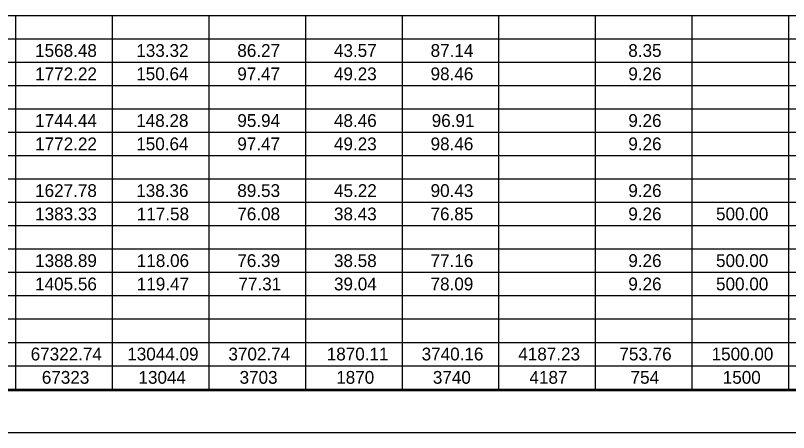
# Model space of a CAD drawing. Extents: x 0 to 34.4, y 0 to 47.
# Drawn here: x 16.38 to 25.65, y 0 to 5 of the extents above; entities that cross this region are included whole.
import ezdxf

# ---------------------------------------------------------------- set-up
doc = ezdxf.new("R2010")
doc.units = 0
for name, color, linetype in [('SH_Border', 7, 'Continuous'), ('SH_Cut_Line', 7, 'Continuous'), ('SH_Text', 7, 'Continuous')]:
    doc.layers.add(name, color=color, linetype=linetype)

msp = doc.modelspace()

# ---------------------------------------------------------------- linework, layer by layer
at = {"layer": 'SH_Border'}
msp.add_lwpolyline([(1.5, 21.5), (33.5, 21.5), (33.5, 0.5), (1.5, 0.5)], close=True, dxfattribs=at)
at = {"layer": 'SH_Cut_Line'}
msp.add_lwpolyline([(0, 0), (34, 0), (34, 22), (0, 22)], close=True, dxfattribs=at)
at = {"layer": 'SH_Text'}
for p, q in [((15.2196, 4.9965), (16.3784, 4.9965)), ((16.3784, 4.9965), (24.4903, 4.9965)), ((16.3784, 4.9965), (16.3784, 4.7168)), ((17.5373, 4.9965), (17.5373, 4.7168)), ((18.6961, 4.9965), (18.6961, 4.7168)), ((19.855, 4.9965), (19.855, 4.7168)), ((21.0138, 4.9965), (21.0138, 4.7168)), ((22.1726, 4.9965), (22.1726, 4.7168)), ((23.3315, 4.9965), (23.3315, 4.7168)), ((24.4903, 4.9965), (25.6492, 4.9965)), ((24.4903, 4.9965), (24.4903, 4.7168)), ((25.6492, 4.9965), (27.9668, 4.9965)), ((25.6492, 4.9965), (25.6492, 4.7168)), ((15.2196, 4.7168), (16.3784, 4.7168)), ((16.3784, 4.7168), (24.4903, 4.7168)), ((16.3784, 4.7168), (16.3784, 4.4371)), ((17.5373, 4.7168), (17.5373, 4.4371)), ((18.6961, 4.7168), (18.6961, 4.4371)), ((19.855, 4.7168), (19.855, 4.4371)), ((21.0138, 4.7168), (21.0138, 4.4371)), ((22.1726, 4.7168), (22.1726, 4.4371)), ((23.3315, 4.7168), (23.3315, 4.4371)), ((24.4903, 4.7168), (25.6492, 4.7168)), ((24.4903, 4.7168), (24.4903, 4.4371)), ((25.6492, 4.7168), (27.9668, 4.7168)), ((25.6492, 4.7168), (25.6492, 4.4371)), ((15.2196, 4.4371), (16.3784, 4.4371)), ((16.3784, 4.4371), (24.4903, 4.4371)), ((16.3784, 4.4371), (16.3784, 4.1574)), ((17.5373, 4.4371), (17.5373, 4.1574)), ((18.6961, 4.4371), (18.6961, 4.1574)), ((19.855, 4.4371), (19.855, 4.1574)), ((21.0138, 4.4371), (21.0138, 4.1574)), ((22.1726, 4.4371), (22.1726, 4.1574)), ((23.3315, 4.4371), (23.3315, 4.1574)), ((24.4903, 4.4371), (25.6492, 4.4371)), ((24.4903, 4.4371), (24.4903, 4.1574)), ((25.6492, 4.4371), (27.9668, 4.4371)), ((25.6492, 4.4371), (25.6492, 4.1574)), ((15.2196, 4.1574), (16.3784, 4.1574)), ((16.3784, 4.1574), (24.4903, 4.1574)), ((16.3784, 4.1574), (16.3784, 3.5979)), ((17.5373, 4.1574), (17.5373, 3.5979)), ((18.6961, 4.1574), (18.6961, 3.5979)), ((19.855, 4.1574), (19.855, 3.5979)), ((21.0138, 4.1574), (21.0138, 3.5979)), ((22.1726, 4.1574), (22.1726, 3.5979)), ((23.3315, 4.1574), (23.3315, 3.5979)), ((24.4903, 4.1574), (25.6492, 4.1574)), ((24.4903, 4.1574), (24.4903, 3.5979)), ((25.6492, 4.1574), (27.9668, 4.1574)), ((25.6492, 4.1574), (25.6492, 3.5979)), ((15.2196, 3.8776), (16.3784, 3.8776)), ((16.3784, 3.8776), (24.4903, 3.8776)), ((24.4903, 3.8776), (25.6492, 3.8776)), ((25.6492, 3.8776), (27.9668, 3.8776)), ((15.2196, 3.5979), (16.3784, 3.5979)), ((16.3784, 3.5979), (24.4903, 3.5979)), ((16.3784, 3.5979), (16.3784, 3.3182)), ((17.5373, 3.5979), (17.5373, 3.3182)), ((18.6961, 3.5979), (18.6961, 3.3182)), ((19.855, 3.5979), (19.855, 3.3182)), ((21.0138, 3.5979), (21.0138, 3.3182)), ((22.1726, 3.5979), (22.1726, 3.3182)), ((23.3315, 3.5979), (23.3315, 3.3182)), ((24.4903, 3.5979), (25.6492, 3.5979)), ((24.4903, 3.5979), (24.4903, 3.3182)), ((25.6492, 3.5979), (27.9668, 3.5979)), ((25.6492, 3.5979), (25.6492, 3.3182)), ((15.2196, 3.3182), (16.3784, 3.3182)), ((16.3784, 3.3182), (24.4903, 3.3182)), ((16.3784, 3.3182), (16.3784, 3.0385)), ((17.5373, 3.3182), (17.5373, 3.0385)), ((18.6961, 3.3182), (18.6961, 3.0385)), ((19.855, 3.3182), (19.855, 3.0385)), ((21.0138, 3.3182), (21.0138, 3.0385)), ((22.1726, 3.3182), (22.1726, 3.0385)), ((23.3315, 3.3182), (23.3315, 3.0385)), ((24.4903, 3.3182), (25.6492, 3.3182)), ((24.4903, 3.3182), (24.4903, 3.0385)), ((25.6492, 3.3182), (27.9668, 3.3182)), ((25.6492, 3.3182), (25.6492, 3.0385)), ((15.2196, 3.0385), (16.3784, 3.0385)), ((16.3784, 3.0385), (24.4903, 3.0385)), ((16.3784, 3.0385), (16.3784, 2.7588)), ((17.5373, 3.0385), (17.5373, 2.7588)), ((18.6961, 3.0385), (18.6961, 2.7588)), ((19.855, 3.0385), (19.855, 2.7588)), ((21.0138, 3.0385), (21.0138, 2.7588)), ((22.1726, 3.0385), (22.1726, 2.7588)), ((23.3315, 3.0385), (23.3315, 2.7588)), ((24.4903, 3.0385), (25.6492, 3.0385)), ((24.4903, 3.0385), (24.4903, 2.7588)), ((25.6492, 3.0385), (27.9668, 3.0385)), ((25.6492, 3.0385), (25.6492, 2.7588)), ((15.2196, 2.7588), (16.3784, 2.7588)), ((16.3784, 2.7588), (24.4903, 2.7588)), ((16.3784, 2.7588), (16.3784, 2.1993)), ((17.5373, 2.7588), (17.5373, 2.1993)), ((18.6961, 2.7588), (18.6961, 2.1993)), ((19.855, 2.7588), (19.855, 2.1993)), ((21.0138, 2.7588), (21.0138, 2.1993)), ((22.1726, 2.7588), (22.1726, 2.1993)), ((23.3315, 2.7588), (23.3315, 2.1993)), ((24.4903, 2.7588), (25.6492, 2.7588)), ((24.4903, 2.7588), (24.4903, 2.1993)), ((25.6492, 2.7588), (27.9668, 2.7588)), ((25.6492, 2.7588), (25.6492, 2.1993)), ((15.2196, 2.479), (16.3784, 2.479)), ((16.3784, 2.479), (24.4903, 2.479)), ((24.4903, 2.479), (25.6492, 2.479)), ((25.6492, 2.479), (27.9668, 2.479)), ((15.2196, 2.1993), (16.3784, 2.1993)), ((16.3784, 2.1993), (24.4903, 2.1993)), ((16.3784, 2.1993), (16.3784, 1.9196)), ((17.5373, 2.1993), (17.5373, 1.9196)), ((18.6961, 2.1993), (18.6961, 1.9196)), ((19.855, 2.1993), (19.855, 1.9196)), ((21.0138, 2.1993), (21.0138, 1.9196)), ((22.1726, 2.1993), (22.1726, 1.9196)), ((23.3315, 2.1993), (23.3315, 1.9196)), ((24.4903, 2.1993), (25.6492, 2.1993)), ((24.4903, 2.1993), (24.4903, 1.9196)), ((25.6492, 2.1993), (27.9668, 2.1993)), ((25.6492, 2.1993), (25.6492, 1.9196)), ((15.2196, 1.9196), (16.3784, 1.9196)), ((16.3784, 1.9196), (24.4903, 1.9196)), ((16.3784, 1.9196), (16.3784, 1.6399)), ((17.5373, 1.9196), (17.5373, 1.6399)), ((18.6961, 1.9196), (18.6961, 1.6399)), ((19.855, 1.9196), (19.855, 1.6399)), ((21.0138, 1.9196), (21.0138, 1.6399)), ((22.1726, 1.9196), (22.1726, 1.6399)), ((23.3315, 1.9196), (23.3315, 1.6399)), ((24.4903, 1.9196), (25.6492, 1.9196)), ((24.4903, 1.9196), (24.4903, 1.6399)), ((25.6492, 1.9196), (27.9668, 1.9196)), ((25.6492, 1.9196), (25.6492, 1.6399)), ((15.2196, 1.6399), (16.3784, 1.6399)), ((16.3784, 1.6399), (24.4903, 1.6399)), ((16.3784, 1.6399), (16.3784, 1.3602)), ((17.5373, 1.6399), (17.5373, 1.3602)), ((18.6961, 1.6399), (18.6961, 1.3602)), ((19.855, 1.6399), (19.855, 1.3602)), ((21.0138, 1.6399), (21.0138, 1.3602)), ((22.1726, 1.6399), (22.1726, 1.3602)), ((23.3315, 1.6399), (23.3315, 1.3602)), ((24.4903, 1.6399), (25.6492, 1.6399)), ((24.4903, 1.6399), (24.4903, 1.3602)), ((25.6492, 1.6399), (27.9668, 1.6399)), ((25.6492, 1.6399), (25.6492, 1.3602)), ((15.2196, 1.3602), (16.3784, 1.3602)), ((16.3784, 1.3602), (24.4903, 1.3602)), ((16.3784, 1.3602), (16.3784, 0.8007)), ((17.5373, 1.3602), (17.5373, 0.8007)), ((18.6961, 1.3602), (18.6961, 0.8007)), ((19.855, 1.3602), (19.855, 0.8007)), ((21.0138, 1.3602), (21.0138, 0.8007)), ((22.1726, 1.3602), (22.1726, 0.8007)), ((23.3315, 1.3602), (23.3315, 0.8007)), ((24.4903, 1.3602), (25.6492, 1.3602)), ((24.4903, 1.3602), (24.4903, 0.8007)), ((25.6492, 1.3602), (27.9668, 1.3602)), ((25.6492, 1.3602), (25.6492, 0.8007)), ((15.2196, 1.0804), (16.3784, 1.0804)), ((16.3784, 1.0804), (24.4903, 1.0804)), ((24.4903, 1.0804), (25.6492, 1.0804)), ((25.6492, 1.0804), (27.9668, 1.0804)), ((15.2196, 0.8007), (16.3784, 0.8007)), ((16.3784, 0.8007), (24.4903, 0.8007)), ((16.3784, 0.8007), (16.3784, 0.521)), ((17.5373, 0.8007), (17.5373, 0.521)), ((18.6961, 0.8007), (18.6961, 0.521)), ((19.855, 0.8007), (19.855, 0.521)), ((21.0138, 0.8007), (21.0138, 0.521)), ((22.1726, 0.8007), (22.1726, 0.521)), ((23.3315, 0.8007), (23.3315, 0.521)), ((24.4903, 0.8007), (25.6492, 0.8007)), ((24.4903, 0.8007), (24.4903, 0.521)), ((25.6492, 0.8007), (27.9668, 0.8007)), ((25.6492, 0.8007), (25.6492, 0.521)), ((15.2196, 0.521), (16.3784, 0.521)), ((16.3784, 0.521), (24.4903, 0.521)), ((24.4903, 0.521), (25.6492, 0.521)), ((25.6492, 0.521), (27.9668, 0.521))]:
    msp.add_line(p, q, dxfattribs=at)

# ---------------------------------------------------------------- texts
for s, p in [('1568.48', (16.6142, 4.5003)), ('133.32', (17.8274, 4.5003)), ('86.27', (19.039, 4.5003)), ('43.57', (20.1978, 4.5003)), ('87.14', (21.357, 4.5003)), ('8.35', (23.7274, 4.5003)), ('1772.22', (16.615, 4.2206)), ('150.64', (17.8269, 4.2206)), ('97.47', (19.039, 4.2206)), ('49.23', (20.1978, 4.2206)), ('98.46', (21.3567, 4.2206)), ('9.26', (23.7279, 4.2206)), ('1744.44', (16.6146, 3.6612)), ('148.28', (17.8265, 3.6612)), ('95.94', (19.0393, 3.6612)), ('48.46', (20.1978, 3.6612)), ('96.91', (21.37, 3.6612)), ('9.26', (23.7279, 3.6612)), ('1772.22', (16.615, 3.3815)), ('150.64', (17.8269, 3.3815)), ('97.47', (19.039, 3.3815)), ('49.23', (20.1978, 3.3815)), ('98.46', (21.3567, 3.3815)), ('9.26', (23.7279, 3.3815)), ('1627.78', (16.6142, 2.822)), ('138.36', (17.8266, 2.822)), ('89.53', (19.039, 2.822)), ('45.22', (20.1986, 2.822)), ('90.43', (21.3567, 2.822)), ('9.26', (23.7279, 2.822)), ('1383.33', (16.6143, 2.5423)), ('117.58', (17.8337, 2.5423)), ('76.08', (19.0389, 2.5423)), ('38.43', (20.1978, 2.5423)), ('76.85', (21.3562, 2.5423)), ('9.26', (23.7279, 2.5423)), ('500.00', (24.7799, 2.5423)), ('1388.89', (16.6142, 1.9829)), ('118.06', (17.8338, 1.9829)), ('76.39', (19.0389, 1.9829)), ('38.58', (20.1977, 1.9829)), ('77.16', (21.3567, 1.9829)), ('9.26', (23.7279, 1.9829)), ('500.00', (24.7799, 1.9829)), ('1405.56', (16.6143, 1.7031)), ('119.47', (17.8338, 1.7031)), ('77.31', (19.0524, 1.7031)), ('39.04', (20.1982, 1.7031)), ('78.09', (21.3566, 1.7031)), ('9.26', (23.7279, 1.7031)), ('500.00', (24.7799, 1.7031)), ('67322.74', (16.561, 0.864)), ('13044.09', (17.7195, 0.864)), ('3702.74', (18.9323, 0.864)), ('1870.11', (20.1113, 0.864)), ('3740.16', (21.2496, 0.864)), ('4187.23', (22.4085, 0.864)), ('753.76', (23.6208, 0.864)), ('1500.00', (24.7264, 0.864)), ('67323', (16.6945, 0.5843)), ('13044', (17.8537, 0.5843)), ('3703', (19.0658, 0.5843)), ('1870', (20.2249, 0.5843)), ('3740', (21.3837, 0.5843)), ('4187', (22.5423, 0.5843)), ('754', (23.755, 0.5843)), ('1500', (24.8602, 0.5843))]:
    msp.add_text(s, height=0.15318, dxfattribs=at).set_placement(p)

doc.saveas('drawing.dxf')
